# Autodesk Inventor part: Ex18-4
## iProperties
Author: Elise Moss
Revision Number: A
Created: 2001-09
Part Number: Ex18-4
Description: ROD, HANDLE
Document SubType Name: Modeling
Designer: Elise Moss
Control State: 0
Master: False
Checked Out: False
PropertySet Name: Design Tracking Control
Length Units: 11272
Angle Units: 11279
Time Units: 11290
Mass Units: 11286
Shininess: 3
Angle Display Precision: 2
Document Length Units: 11272
Document Angle Units: 11286
Document Time Units: 11279
Document Mass Units: 11290
Document Length Units Precision: 3
Document Angle Units Precision: 0
Compacted: False
PropertySet Name: _Private Model Information
Density: 0.0
Volumn: 0.0
Area: 0.0
PropertySet Name: Model Information
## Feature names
1. Revolution1
